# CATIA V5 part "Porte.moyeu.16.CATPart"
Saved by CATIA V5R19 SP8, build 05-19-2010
Part number: Porte.moyeu.16
Bounding box of the stored display mesh (mm): x -21.25 to 5, y -10.5 to 10.5, z -9.5 to 13
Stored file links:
  G:\EU_thinkMotion\CFAO_2010\MMS_groupe3\MMS_groupe3\jbonnamy\jbonnamy_cfao\Porte.moyeu.16.CATPart
  G:\EU_thinkMotion\CFAO_2010\MMS_groupe3\MMS_groupe3\jbonnamy\jbonnamy_cfao\jbonnamy_suspension.arriere.directionnelle.CATProduct
  G:\EU_thinkMotion\CFAO_2010\MMS_groupe3\MMS_groupe3\jbonnamy\jbonnamy_cfao\Bras.1.CATPart
  G:\EU_thinkMotion\CFAO_2010\MMS_groupe3\MMS_groupe3\jbonnamy\jbonnamy_cfao\SKL.porte.moyeu.16.CATPart
  G:\EU_thinkMotion\CFAO_2010\MMS_groupe3\MMS_groupe3\jbonnamy\jbonnamy_cfao\SKL.general.CATPart
  C:\Users\Micheline\Desktop\projet CFAO\Nouveau dossier\temp\Nouveau dossier\SKL.centrage.et.fixation.moyeu.CATPart
  G:\EU_thinkMotion\CFAO_2010\MMS_groupe3\MMS_groupe3\jbonnamy\jbonnamy_cfao\Vis.sans.fin.CATPart
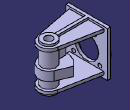
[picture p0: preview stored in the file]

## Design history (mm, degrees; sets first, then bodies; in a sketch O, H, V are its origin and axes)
External parameters (linked from other documents)
  External.Hauteur.porte.moyeu = 22.5 mm
  External.Diametre.vis.12 = 3.95 mm
  External.Diametre.fixation.22.24.ext = 7.5 mm
  External.Distance.fixation.24.centre.pignon = 9.5 mm
  External.Distance.centre.pivot.moyeu = 20.5 mm
  External.Epaisseur.support.10 = 1.5 mm
  External.Rayon.renfort.porte.moyeu = 5 mm
  External.Largeur.porte.moyeu = 21 mm
  External.Diametre.primitif.roue = 18 mm
  External.Epaisseur.roue = 4.5 mm
  External.Diametre.vis.fixation = 2 mm
Set1
  Line1 "Axe.pivot": linked copy from another document
  Plane1 "Plan.sup.porte.moyeu": linked copy from another document
  Point1 "Centre.pignon": linked copy from another document
  Plane2 "Plan.inf.porte.moyeu": linked copy from another document
  Plane3 "Plan.moyeu": linked copy from another document
  Point2 "Point.vis.sans.fin": linked copy from another document
Body1 (main body)
  Sketch1 on yz-plane, origin (0, 0, 0), H (0, 1, 0), V (0, 0, 1)
    line L1 (1.975, 13) -> (3.75, 13)
    line L2 (3.75, 13) -> (3.75, -9.5)
    line L3 (3.75, -9.5) -> (1.975, -9.5)
    line L4 (1.975, -9.5) -> (1.975, 13)
    reference projected line E1 (0, -25) -> (0, 25) from Line1
    reference projected line E2 (0, -25) -> (0, 25) from Line1
    distance L4 E1 = 1.975 {= External.Diametre.vis.12 /2}
    distance L2 E2 = 3.75 {= External.Diametre.fixation.22.24.ext /2}
    distance L1 L3 = 22.5 {= External.Hauteur.porte.moyeu}
    distance L3 H = 9.5 {= External.Distance.fixation.24.centre.pignon}
  Shaft1: profile Sketch1, axis Line1, angle 360
  Sketch2 on zx-plane, origin (0, 0, 0), H (-1, 0, 0), V (0, 0, 1)
    line L1 (19, 13) -> (3.75, 13)
    line L2 (3.75, 13) -> (3.75, -9.5)
    line L3 (3.75, -9.5) -> (19, -9.5)
    line L4 (19, -9.5) -> (19, -6.75)
    line L5 (19, -6.75) -> (7.75, -6.75)
    line L6 (7.75, -6.75) -> (7.75, 6.7)
    line L7 (7.75, 6.7) -> (19, 6.7)
    line L8 (19, 6.7) -> (19, 13)
    reference projected line E1 (0, -25) -> (0, 25) from Line1
    distance L8 L4 = 0
    distance L1 L7 = 6.3
    distance L5 L3 = 2.75
    distance L8 L2 = 15.25 {= External.Distance.centre.pivot.moyeu -External.Diametre.fixation.22.24.ext /2-External.Epaisseur.support.10}
    distance L6 L2 = 4
    distance L2 E1 = 3.75 {= External.Diametre.fixation.22.24.ext /2}
    distance L3 H = 9.5 {= External.Distance.fixation.24.centre.pignon}
    distance L3 L1 = 22.5 {= External.Hauteur.porte.moyeu}
  Pad1: profile Sketch2, direction (0, 1, 0), length 0.75 {= External.Epaisseur.support.10 /2}, opposite side length 0.75 {= External.Epaisseur.support.10 /2}
  Sketch3 on Plane1, origin (0, 0, 12), H (1, 0, 0), V (0, 1, 0)
    arc A1 centre (0, 0) radius 5 from (0.521, -4.9728) to (0.2991, 4.991) ccw
    point P1 (0, 0)
    point P2 (-20.5, 9)
    line L1 (-20.5, 9) -> (-20.5, -9)
    line L2 (-20.5, -9) -> (0.521, -4.9728)
    line L3 (-20.5, 9) -> (0.2991, 4.991)
    reference projected point E1 (0, 0) from Point1
    circle A2 centre (0, 0) radius 3.75
    point P6 (0, 0)
    reference projected point E2 (0, 0) from Point1
    radius A1 = 5 {= External.Rayon.renfort.porte.moyeu}
    length L1 = 18 {= External.Largeur.porte.moyeu -2*External.Epaisseur.support.10}
    distance P1 E1 = 0
    distance L1 V = 20.5 {= External.Distance.centre.pivot.moyeu}
    radius A2 = 3.75 {= External.Diametre.fixation.22.24.ext /2}
    distance P6 E2 = 0
    distance P2 H = 9 {= External.Largeur.porte.moyeu /2-External.Epaisseur.support.10}
  Pad2: profile Sketch3, direction (0, 0, -1), length 1.5 {= External.Epaisseur.support.10}
  Sketch4 on Plane2, origin (0, 0, -8), H (1, 0, 0), V (0, 1, 0)
    point P1 (0, 0)
    circle A1 centre (0, 0) radius 3.75
    point P2 (0, 0)
    reference projected point E1 (0, 0) from Point1
    point P3 (-20.5, 9)
    line L1 (-20.5, 9) -> (-20.5, -9)
    reference projected point E2 (0, 0) from Point1
    arc A2 centre (0, 0) radius 5 from (0.6057, -4.9632) to (0.6057, 4.9632) ccw
    point P5 (0, 0)
    reference projected point E3 (0, 0) from Point1
    line L2 (-20.5, -9) -> (0.6057, -4.9632)
    line L3 (-20.5, 9) -> (0.6057, 4.9632)
    radius A1 = 3.75 {= External.Diametre.fixation.22.24.ext /2}
    distance P2 E1 = 0
    length L1 = 18 {= External.Largeur.porte.moyeu -2*External.Epaisseur.support.10}
    distance P1 E2 = 0
    distance P3 H = 9 {= External.Largeur.porte.moyeu /2-External.Epaisseur.support.10}
    radius A2 = 5 {= External.Rayon.renfort.porte.moyeu}
    distance P5 E3 = 0
    distance L1 V = 20.5 {= External.Distance.centre.pivot.moyeu}
  Pad3: profile Sketch4, direction (0, 0, 1), length 1.5 {= External.Epaisseur.support.10}
  Sketch5 on Plane3, origin (-20.5, 0, 0), H (0, 1, 0), V (0, 0, 1)
    line L1 (10.5, 13) -> (-10.5, 13)
    line L2 (-10.5, 13) -> (-10.5, -9.5)
    line L3 (-10.5, -9.5) -> (10.5, -9.5)
    line L4 (10.5, -9.5) -> (10.5, 13)
    distance L2 L4 = 21 {= External.Largeur.porte.moyeu}
    distance L1 L3 = 22.5 {= External.Hauteur.porte.moyeu}
    distance L2 V = 10.5 {= External.Largeur.porte.moyeu /2}
    distance L3 H = 9.5 {= External.Distance.fixation.24.centre.pignon}
  Pad4: profile Sketch5, direction (1, 0, 0), length 1.5 {= External.Epaisseur.support.10}
  Sketch6 on xy-plane, origin (0, 0, 0), H (1, 0, 0), V (0, 1, 0)
    arc A1 centre (0, 0) radius 5 from (1.929, -4.6129) to (1.929, 4.6129) ccw
    point P1 (0, 0)
    point P2 (0, 0)
    reference projected point E1 (0, 0) from Point1
    reference projected point E2 (0, 0) from Point1
    arc A2 centre (0, 0) radius 9 from (-4.9749, 7.5) to (-4.9749, -7.5) ccw
    point P3 (0, 0)
    point P4 (-4.9749, 7.5)
    point P5 (-4.9749, -7.5)
    reference projected point E3 (0, 0) from Point1
    line L1 (-4.9749, 7.5) -> (1.929, 4.6129)
    line L2 (-4.9749, -7.5) -> (1.929, -4.6129)
    radius A1 = 5 {= External.Rayon.renfort.porte.moyeu}
    distance P1 E1 = 0
    distance P2 E2 = 0
    radius A2 = 9 {= External.Diametre.primitif.roue /2}
    distance P4 P5 = 15
    distance P3 E3 = 0
  Pad5: profile Sketch6, direction (0, 0, 1), length 2.25 {= External.Epaisseur.roue /2}, opposite side length 2.25 {= External.Epaisseur.roue /2}
  Sketch7 on Plane3, origin (-20.5, 0, 0), H (0, 1, 0), V (0, 0, 1)
    construction arc A1 centre (0, 0) radius 8.25 from (-4, 7.2154) to (-6.5622, -5) ccw
    point P1 (-4, 7.2154)
    point P2 (-6.5622, -5)
    arc A2 centre (-4, 7.2154) radius 1.75 from (-4.8485, 8.746) to (-3.1515, 5.6849) cw
    arc A3 centre (-6.5622, -5) radius 1.75 from (-5.1702, -3.9394) to (-7.9542, -6.0606) cw
    arc A4 centre (0, 0) radius 6.5 from (-3.1515, 5.6849) to (-5.1702, -3.9394) ccw
    arc A5 centre (0, 0) radius 10 from (-7.9542, -6.0606) to (-4.8485, 8.746) cw
    construction arc A6 centre (0, 0) radius 8.25 from (6.5622, -5) to (4, 7.2154) ccw
    point P8 (4, 7.2154)
    point P9 (6.5622, -5)
    arc A7 centre (6.5622, -5) radius 1.75 from (7.9542, -6.0606) to (5.1702, -3.9394) cw
    arc A8 centre (4, 7.2154) radius 1.75 from (3.1515, 5.6849) to (4.8485, 8.746) cw
    arc A9 centre (0, 0) radius 6.5 from (5.1702, -3.9394) to (3.1515, 5.6849) ccw
    arc A10 centre (0, 0) radius 10 from (4.8485, 8.746) to (7.9542, -6.0606) cw
    distance P1 V = 4
    distance P2 H = 5
    radius A1 = 8.25
    radius A3 = 1.75
    distance P8 V = 4
    distance P9 H = 5
    radius A6 = 8.25
    radius A8 = 1.75
  Pad6: profile Sketch7, direction (-1, 0, 0), length 0.75 {= External.Epaisseur.support.10 /2}
  Sketch8 on Plane3, origin (-20.5, 0, 0), H (0, 1, 0), V (0, 0, 1)
    circle A1 centre (0, 0) radius 6
    point P1 (0, 0)
    circle A2 centre (-4, 7.2154) radius 1
    point P2 (-4, 7.2154)
    circle A3 centre (-6.5622, -5) radius 1
    point P3 (-6.5622, -5)
    circle A4 centre (6.5622, -5) radius 1
    point P4 (6.5622, -5)
    circle A5 centre (4, 7.2154) radius 1
    point P5 (4, 7.2154)
    reference projected point E1 (0, 0) from Point2
    reference projected point E2 (0, 0) from Point1
    reference projected point E3 (0, 0) from Point1
    reference projected point E4 (0, 0) from Point1
    reference projected point E5 (0, 0) from Point1
    radius A1 = 6
    radius A5 = 1 {= External.Diametre.vis.fixation /2}
    radius A2 = 1 {= External.Diametre.vis.fixation /2}
    radius A3 = 1 {= External.Diametre.vis.fixation /2}
    radius A4 = 1 {= External.Diametre.vis.fixation /2}
    distance P1 E1 = 0
    distance P2 V = 4
    distance P5 V = 4
    distance P3 H = 5
    distance P4 H = 5
    distance P2 E2 = 8.25
    distance P3 E3 = 8.25
    distance P5 E4 = 8.25
    distance P4 E5 = 8.25
  Pocket1: profile Sketch8, direction (1, 0, 0), length 1.5 {= External.Epaisseur.support.10}, opposite side length 1.5 {= External.Epaisseur.support.10}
